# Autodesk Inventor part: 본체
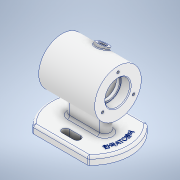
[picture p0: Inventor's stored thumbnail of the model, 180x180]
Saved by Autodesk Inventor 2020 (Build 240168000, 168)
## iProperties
Created: 2022-02
Part Number: 본체
Material: 알루미늄 6061
Document SubType Name: Modeling
Designer: 602-01
Density: 2.7 g/cm^3
Appearance: 알루미늄 - 평지
Mass: 483.257 g
Surface Area: 488.124 cm^2
Volume: 178.984 cm^3
Author: 602-01
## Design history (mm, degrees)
sketch "스케치1"
  geometry: L1 (-36, 0)-(36, 0); L2 (-36, 0)-(-36, 30); L3 (-36, 30)-(36, 30); L4 (36, 30)-(36, 0); L5 (-36, 16)-(-24, 16); L6 (-24, 16)-(-24, 14); L7 (-24, 14)-(-20, 14); L8 (-20, 14)-(-20, 25); L9 (-20, 25)-(20, 25); L10 (20, 25)-(20, 14); L11 (24, 14)-(24, 16); L12 (24, 16)-(36, 16); L13 (20, 14)-(24, 14); 2 further points
  constraints: 26 end point, 7 perpendicular, 2 horizontal, 2 parallel, 2 point on line, 1 coincident, 1 midpoint, 1 vertical
  dimensions: "d5" = 32 diameter of L5 L1; "d6" = 28 diameter of L7 L1; "d7" = 50 diameter of L9 L1; "d8" = 28 diameter of L13 L1; "d9" = 32 diameter of L12 L1; "d10" = 60 diameter of L3 L1; "d11" = 12 distance of L5.start L5.end; "d12" = 40 distance of L8.end L9.end; "d13" = 12 distance of L11.end L12.end; "d14" = 72 distance of L2.end L3.end; "d15" = 48 distance of L11.end L5.end (derived); "d16" = 4 distance of L10.end L11.start; "d17" = 4 distance of L6.end L7.end
revolve "회전1" sketch "스케치1" stored, may be unused: angle "d18" = 360 deg
node "작업 평면1"
sketch "스케치2"
  geometry: L1 (-52, 38)-(52, 38); L2 (52, 38)-(52, -38); L3 (52, -38)-(-52, -38); L4 (-52, -38)-(-52, 38); L5 (-52, 38)-(52, -38); L6 (52, 38)-(-52, -38); L7 (0, 38)-(0, -38); A1 r 52 centre (0, 0) between (-35.496, 38) and (-35.496, -38); A2 r 52 centre (0, 0) between (35.496, -38) and (35.496, 38); 5 further points
  constraints: 14 end point, 6 midpoint, 5 point on circle, 2 centre point, 2 parallel, 2 point on line, 2 symmetric about line, 1 coincident, 1 horizontal, 1 perpendicular, 1 other
  dimensions: "d20" = 76 distance of L1.end L2.end; "d22" = 52 radius of A1
extrude "돌출1" join sketch "스케치2" distance "d23" = 10; taper "d24" = 0 deg
sketch "스케치3"
  geometry: L1 (26, -7)-(-26, -7); L2 (-26, -7)-(-26, 7); L3 (-26, 7)-(26, 7); L4 (26, 7)-(26, -7); L5 (26, -7)-(-26, 7); L6 (-26, -7)-(26, 7); 1 further point
  constraints: 12 end point, 2 midpoint, 2 parallel, 1 horizontal, 1 perpendicular
  dimensions: "d25" = 52 distance of L2.end L3.end; "d26" = 14 distance of L1.end L2.end
extrude "돌출2" join sketch "스케치3" stored distance "d27" = 10; taper "d28" = 0 deg
fillet "모깎기1" dims "d29" = 7
fillet "모깎기2" dims "d30" = 3
sketch "스케치4"
  geometry: L1 (7.5, -24)-(-7.5, -24); L2 (7.5, -19.5)-(-7.5, -19.5); L3 (-7.5, -28.5)-(7.5, -28.5); L4 (0, 0)-(52, 0); L5 (7.5, 24)-(-7.5, 24); L6 (7.5, 19.5)-(-7.5, 19.5); L7 (-7.5, 28.5)-(7.5, 28.5); A1 r 4.5 centre (7.5, -24) between (7.5, -28.5) and (7.5, -19.5); A2 r 4.5 centre (-7.5, -24) between (-7.5, -19.5) and (-7.5, -28.5); A3 r 52 centre (0, 0) between (35.496, -38) and (35.496, 38) reference; A4 r 4.5 centre (7.5, 24) between (7.5, 19.5) and (7.5, 28.5); A5 r 4.5 centre (-7.5, 24) between (-7.5, 28.5) and (-7.5, 19.5); 2 further points
  constraints: 18 end point, 9 point on circle, 7 symmetric about line, 4 centre point, 4 tangent, 2 horizontal, 1 midpoint, 1 parallel, 1 vertical alignment, 2 other
  dimensions: "d31" = 15 distance of L1.end L1.start; "d32" = 4.5 radius of A1; "d33" = 24 vertical distance of L4.start L1.end
extrude "돌출3" cut sketch "스케치4" extent not by distance; stored distance "d34" = 70; taper "d35" = 0 deg
sketch "스케치5"
  geometry: C1 r 42.5 at (0, 0); 1 further point
  constraints: 1 centre point, 1 coincident, 1 other
  dimensions: "d36" = 85 diameter of C1
feature "엠보싱1" sketch "스케치5" dims "d37" = 0.5, "d38" = 0
sketch "스케치6"
  geometry: 2 further points
  constraints: 1 vertical alignment
  dimensions: "d39" = 23 distance of point (0, 23) point (0, 0)
hole "구멍1" sketch "스케치6" at (0, 23) diameter "d40" = 3.242; stored, may be unused: countersink angle "d44" = 90 deg, drill point angle "d46" = 120 deg; dims "d41" = 8, "d42" = 4, "d43" = 2, "d45" = 10
sketch "스케치7"
  geometry: 2 further points
  constraints: 1 vertical alignment
  dimensions: "d50" = 23 distance of point (0, 0) point (0, 23)
hole "구멍2" sketch "스케치7" at (0, 23) diameter "d51" = 3.242; stored, may be unused: countersink angle "d55" = 90 deg, drill point angle "d57" = 120 deg; dims "d52" = 8, "d53" = 4, "d54" = 2, "d56" = 10
fillet "모깎기3" dims "d73" = 3
fillet "모깎기4" dims "d74" = 3
fillet "모깎기5" dims "d75" = 3
fillet "모깎기6" dims "d76" = 0.3
chamfer "모따기1" distance "d77" = 1; stored, may be unused: second distance "d78" = 2, angle "d79" = 45 deg
sketch "스케치11"
  geometry: L1 (0, 0)-(30, 0); L2 (0, 0)-(28.579, -16.5); 1 further point
  constraints: 4 end point, 1 horizontal, 1 horizontal alignment, 1 other
  dimensions: "d80" = 30 deg angle of L2 L1; "d81" = 33 distance of L1.start L2.end
node "작업 평면3"
sketch "스케치12"
  geometry: C1 r 8 at (0, 0); 1 further point
  constraints: 1 centre point, 1 coincident
  dimensions: "d82" = 16 diameter of C1
extrude "돌출5" join sketch "스케치12" stored distance "d83" = 10; taper "d84" = 0 deg
sketch "스케치13"
  geometry: C1 r 8 at (0, 0) reference; 2 further points
  constraints: 1 coincident
hole "구멍4" sketch "스케치13" at (0, 0) diameter "d85" = 8; stored, may be unused: countersink angle "d89" = 90 deg, drill point angle "d91" = 0 deg; dims "d86" = 8, "d87" = 4, "d88" = 2, "d90" = 10
fillet "모깎기7" dims "d92" = 1
node "솔리드1"
pattern_circular "원형 패턴1" dims angle "d48" = 360 deg
pattern_circular "원형 패턴2" dims angle "d59" = 360 deg
feature "A9D066F2-1C7D-4E18-AEED-F7BC21143FA4" dims "d51" = 3.242, "d52" = 8, "d53" = 4, "d54" = 2, "d55" = 90 deg, "d56" = 10, "d57" = 120 deg
other parameters: "d19" = -62
